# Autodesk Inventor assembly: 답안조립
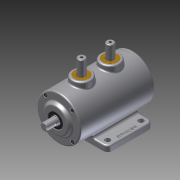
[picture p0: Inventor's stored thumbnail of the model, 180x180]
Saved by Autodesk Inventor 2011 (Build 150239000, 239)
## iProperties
Created: 2014-12
Part Number: 답안조립
Document SubType Name: Assembly
Designer: user
Author: user
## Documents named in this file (10)
- D:\441225V1006\답안조립.iam
- D:\441225V1006\M4-소켓머리.ipt
- D:\441225V1006\1본체.ipt
- D:\441225V1006\2축.ipt
- D:\441225V1006\뒷커버.ipt
- D:\441225V1006\베어링 6203.ipt
- D:\441225V1006\부시.ipt
- D:\441225V1006\슬라이더.ipt
- D:\441225V1006\앞커버.ipt
- D:\441225V1006\오일실.ipt
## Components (13 placed, 5 different names)
1. 1본체:1
2. 2축:1 — 각도:1
3. 7-베어링 6203:1
4. 8-오일실:1
5. 7-베어링 6203:2
6. 9-M4-소켓머리:1
7. 9-M4-소켓머리:2
8. 9-M4-소켓머리:3
9. 9-M4-소켓머리:4
10. 9-M4-소켓머리:5
11. 9-M4-소켓머리:6
12. 9-M4-소켓머리:7
13. 9-M4-소켓머리:8
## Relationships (1: Angle 1)
- 각도:1 [Angle]: 2축:1
